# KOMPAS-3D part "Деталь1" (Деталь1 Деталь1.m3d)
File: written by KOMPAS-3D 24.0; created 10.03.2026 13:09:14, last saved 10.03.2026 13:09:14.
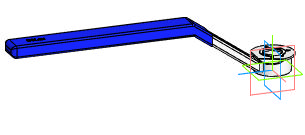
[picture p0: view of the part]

Document properties: Автор: R2D2; Полное имя файла: E:\Работа\Зайцев\BV3232P(4pc)-FP-3WL-F-ISO-H Кран шаровой DN.ru Ду15-100 Ру16\DN80\исходные материалы\Деталь1 Деталь1.m3d

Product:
- Body: Твердое тело1  | qty 1
- Part/product: Деталь1
    additional columns: Типовые

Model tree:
1. Твердое тело1  (labels: Твердое тело1)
